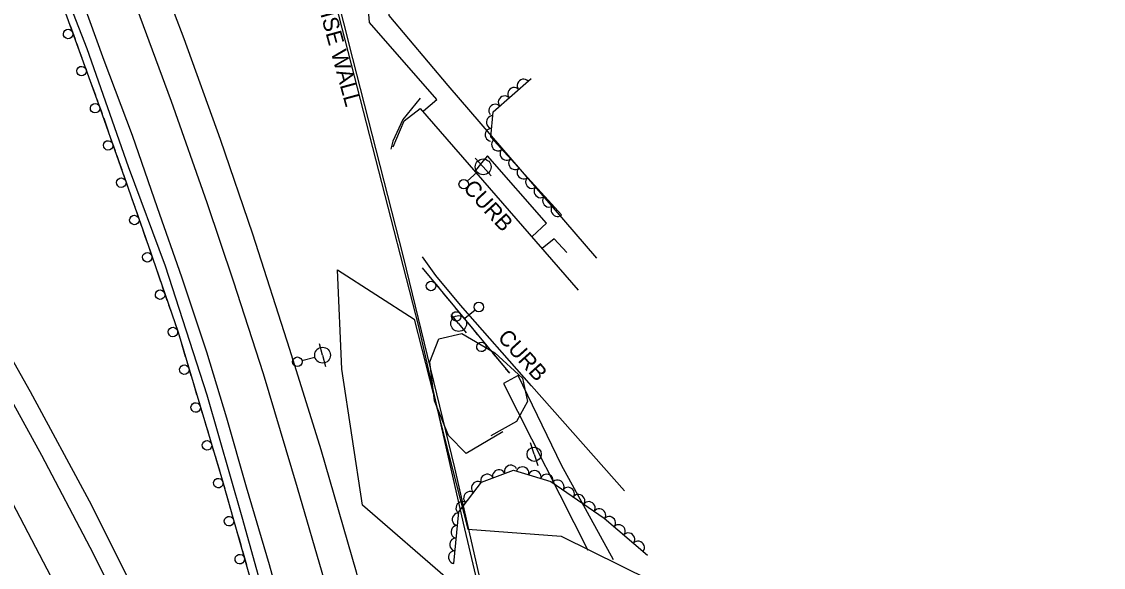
# Model space of a CAD drawing. Extents: x 1722896 to 1754269, y 648279 to 666297.
# Drawn here: x 1726282.7 to 1726624.9, y 657470 to 657642.7 of the extents above; entities that cross this region are included whole.
import ezdxf

# ---------------------------------------------------------------- set-up
doc = ezdxf.new("R2010")
doc.units = 0
for name, color, linetype in [('DESIGN - CENTERLINE - Proposed Text', 7, 'Continuous'), ('DESIGN - SCRATCH - User 1', 7, 'Continuous'), ('SURVEY - CENTERLINE - Preliminary', 7, 'Continuous'), ('SURVEY - CENTERLINE - Preliminary Text', 7, 'Continuous'), ('SURVEY - DTM - Breaklines', 7, 'Continuous'), ('SURVEY - VEGETATION - Features with Text', 7, 'Continuous')]:
    doc.layers.add(name, color=color, linetype=linetype)

msp = doc.modelspace()

# ---------------------------------------------------------------- linework, layer by layer
at = {"layer": 'DESIGN - CENTERLINE - Proposed Text'}
for points in [[(1726409.87, 657614.48), (1726414.08, 657618.02), (1726392.75, 657642.41), (1726388.25, 657697.4), (1726384.31, 657746.16), (1726380.71, 657777.8), (1726371.22, 657832.71)], [(1726378, 657832.59), (1726385.8, 657784.53), (1726390.16, 657748.13), (1726393.5, 657715.1), (1726395.2, 657683.32), (1726398.89, 657644.68), (1726417.54, 657622.52), (1726464.54, 657567.84)], [(1726444.2, 657574.69), (1726448.7, 657578.96), (1726430.09, 657600.24), (1726428.18, 657598.02), (1726425.92, 657595.15)], [(1726455.15, 657569.61), (1726451.17, 657574.02), (1726447.4, 657570.9)], [(1726439.78, 657530.69), (1726435.12, 657528.16), (1726461.82, 657475.47)], [(1726469.89, 657472.36), (1726453.51, 657502.39), (1726439.78, 657530.69)]]:
    msp.add_lwpolyline(points, dxfattribs=at)
at = {"layer": 'DESIGN - SCRATCH - User 1'}
for points in [[(1726250.96, 657761.4), (1726256.98, 657742.64), (1726264.82, 657720.98), (1726275.09, 657698.59), (1726283.23, 657679), (1726294.43, 657651.26), (1726306.95, 657616.94), (1726321.04, 657576.78), (1726332.17, 657544.39), (1726345.94, 657498.45), (1726358.6, 657453.83), (1726365.48, 657423.42), (1726367.67, 657403.38)], [(1726381, 657652.21), (1726408.22, 657546.19), (1726422.41, 657484.03), (1726439.94, 657409.35), (1726459.75, 657325.68), (1726476.24, 657252.3), (1726500.59, 657156.7), (1726516.86, 657091.32), (1726548.53, 656966.41), (1726558.67, 656932.24), (1726559.63, 656932.77), (1726548.98, 656968.62), (1726531.75, 657035.9), (1726512.24, 657113.95), (1726500.6, 657160.92), (1726473.14, 657270.05), (1726457.98, 657336.92), (1726437.8, 657422.18), (1726419.74, 657501.54), (1726403.46, 657568.29), (1726387.43, 657631.08), (1726373.33, 657687.09)], [(1726298.01, 657641.44), (1726299.59, 657637.12)], [(1726300.14, 657635.62), (1726300.94, 657633.41)], [(1726300.94, 657633.41), (1726301.75, 657631.2)], [(1726302.3, 657629.7), (1726303.87, 657625.38)], [(1726304.42, 657623.87), (1726305.23, 657621.67)], [(1726305.23, 657621.67), (1726306.03, 657619.46)], [(1726306.58, 657617.96), (1726306.95, 657616.94), (1726308.12, 657613.62)], [(1726408.74, 657618.52), (1726403.32, 657611.7), (1726400.08, 657604.84), (1726399.5, 657602.29)], [(1726308.65, 657612.11), (1726309.43, 657609.89)], [(1726309.43, 657609.89), (1726310.2, 657607.68)], [(1726310.73, 657606.17), (1726312.26, 657601.83)], [(1726312.79, 657600.32), (1726313.56, 657598.1)], [(1726313.56, 657598.1), (1726314.34, 657595.88)], [(1726314.87, 657594.37), (1726316.39, 657590.03)], [(1726316.92, 657588.52), (1726317.7, 657586.3)], [(1726317.7, 657586.3), (1726318.48, 657584.08)], [(1726319.01, 657582.58), (1726320.53, 657578.23)], [(1726321.06, 657576.72), (1726321.82, 657574.5)], [(1726321.82, 657574.5), (1726322.59, 657572.28)], [(1726323.11, 657570.77), (1726324.6, 657566.42)], [(1726325.12, 657564.9), (1726325.89, 657562.68)], [(1726325.89, 657562.68), (1726326.65, 657560.46)], [(1726409.39, 657564.81), (1726437, 657531.46)], [(1726409.39, 657564.81), (1726410.89, 657562.99)], [(1726327.17, 657558.94), (1726328.66, 657554.59)], [(1726411.91, 657561.76), (1726414.84, 657558.22)], [(1726415.86, 657556.99), (1726417.36, 657555.18)], [(1726417.36, 657555.18), (1726418.86, 657553.37)], [(1726329.18, 657553.08), (1726329.95, 657550.86)], [(1726419.88, 657552.13), (1726422.81, 657548.59)], [(1726329.95, 657550.86), (1726330.71, 657548.64)], [(1726331.23, 657547.12), (1726332.17, 657544.39), (1726332.66, 657542.75)], [(1726423.83, 657547.36), (1726425.33, 657545.55)], [(1726425.33, 657545.55), (1726426.83, 657543.74)], [(1726427.85, 657542.51), (1726430.79, 657538.96)], [(1726333.12, 657541.22), (1726333.79, 657538.97)], [(1726333.79, 657538.97), (1726334.47, 657536.72)], [(1726334.93, 657535.18), (1726336.25, 657530.78)], [(1726431.8, 657537.73), (1726433.3, 657535.92)], [(1726433.3, 657535.92), (1726434.8, 657534.11)], [(1726435.82, 657532.88), (1726437, 657531.46)], [(1726336.71, 657529.24), (1726337.38, 657526.99)], [(1726337.38, 657526.99), (1726338.06, 657524.74)], [(1726338.52, 657523.21), (1726339.84, 657518.8)], [(1726340.3, 657517.27), (1726340.97, 657515.02)], [(1726340.97, 657515.02), (1726341.65, 657512.77)], [(1726342.11, 657511.24), (1726343.43, 657506.83)], [(1726343.89, 657505.3), (1726344.56, 657503.05)], [(1726344.56, 657503.05), (1726345.24, 657500.8)], [(1726345.7, 657499.26), (1726345.94, 657498.45), (1726346.97, 657494.84)], [(1726347.4, 657493.3), (1726348.04, 657491.04)], [(1726348.04, 657491.04), (1726348.69, 657488.78)], [(1726349.12, 657487.24), (1726350.38, 657482.82)], [(1726350.81, 657481.28), (1726351.46, 657479.02)], [(1726351.46, 657479.02), (1726352.1, 657476.76)], [(1726352.53, 657475.22), (1726353.79, 657470.79)]]:
    msp.add_lwpolyline(points, dxfattribs=at)
for centre, start, end in [((1726297.38, 657638.79), 133.3123, 133.3025), ((1726301.67, 657627.04), 133.3123, 133.3025), ((1726305.93, 657615.31), 132.593, 132.5832), ((1726310.07, 657603.52), 132.593, 132.5832), ((1726314.21, 657591.72), 132.593, 132.5832), ((1726318.35, 657579.93), 132.593, 132.5832), ((1726322.43, 657568.13), 132.2196, 132.2097), ((1726412.21, 657559.05), 152.8791, 152.8692), ((1726326.49, 657556.3), 132.2196, 132.2097), ((1726420.18, 657549.42), 152.8791, 152.8692), ((1726330.55, 657544.48), 132.2196, 132.2097), ((1726428.15, 657539.79), 152.8791, 152.8692), ((1726334.15, 657532.57), 129.9498, 129.94), ((1726337.74, 657520.6), 129.9498, 129.94), ((1726341.33, 657508.62), 129.9498, 129.94), ((1726344.89, 657496.67), 129.0987, 129.0889), ((1726348.3, 657484.64), 129.0987, 129.0889), ((1726351.71, 657472.62), 129.0987, 129.0889)]:
    msp.add_arc(centre, 1.5, start, end, dxfattribs=at)
at = {"layer": 'SURVEY - CENTERLINE - Preliminary'}
msp.add_lwpolyline([(1726515.09, 657025.05), (1726489.29, 657121.29), (1726463.71, 657240.55), (1726444.45, 657331.62), (1726429.77, 657395.73), (1726418.25, 657465.7), (1726390.51, 657489.71), (1726384.01, 657532.78), (1726382.66, 657564.12), (1726406.89, 657548.59), (1726423.84, 657482.1), (1726453.33, 657479.87), (1726481.71, 657465.86), (1726509.72, 657351.89), (1726530.14, 657272.08), (1726508.58, 657266.33), (1726481.22, 657265.77), (1726497.24, 657227.31), (1726541.41, 657225.54), (1726567.72, 657118.08), (1726516.19, 657112.72), (1726535.96, 657075.42), (1726549.82, 656999.98)], dxfattribs=at)
at = {"layer": 'SURVEY - CENTERLINE - Preliminary Text'}
for points in [[(1726624.92, 656668.84), (1726597.45, 656736.24), (1726571.93, 656799.16), (1726549.81, 656855.52), (1726526.71, 656918.48), (1726505.02, 656985.71), (1726486.6, 657049.96), (1726469.03, 657114.38), (1726454.34, 657180.42), (1726441.65, 657239.2), (1726427.83, 657298.54), (1726416.2, 657352.6), (1726401.91, 657416.92), (1726388.61, 657468.49), (1726377.49, 657507.19), (1726367.56, 657538.93), (1726355.86, 657575.45), (1726345.64, 657605.36), (1726334.13, 657637.26), (1726321.92, 657669.44), (1726313.29, 657690.92), (1726305.45, 657709.59), (1726303.2, 657708.59)], [(1726411.26, 657223.24), (1726400.11, 657257.01), (1726390.99, 657282.14), (1726381.75, 657306.04), (1726373.51, 657325.94), (1726364.93, 657347.27), (1726356.75, 657365.6), (1726348.52, 657383.83), (1726339.48, 657404.47), (1726329.71, 657425.89), (1726317.16, 657450.98), (1726304.37, 657476.29), (1726289.1, 657505.38), (1726273.06, 657534.46), (1726255.11, 657565.24), (1726237.19, 657594.83), (1726218.79, 657624.35), (1726197.87, 657657.58), (1726178.77, 657685.88), (1726168.64, 657701.01)], [(1726166.72, 657676.7), (1726192.24, 657638.35), (1726215.86, 657600.47), (1726236.72, 657566.96), (1726256.68, 657532.57), (1726274.74, 657499.79), (1726291.93, 657467.18), (1726307.1, 657437.05), (1726319.24, 657412.28), (1726344.84, 657355.24), (1726355.81, 657329.47), (1726366.13, 657303.39), (1726375.2, 657279.85), (1726383.1, 657258.46), (1726390.21, 657239.04), (1726397.63, 657218.88), (1726414.95, 657166.17), (1726425.91, 657130.97), (1726435.08, 657101.5), (1726443.42, 657074.08), (1726458.04, 657025.03)], [(1726265.48, 657560.85), (1726285.34, 657525.65), (1726304.04, 657491.11), (1726323.34, 657452.56), (1726340.43, 657417.82), (1726355.1, 657385.56), (1726368.44, 657355.69), (1726380.6, 657326.49), (1726391.92, 657297.02), (1726398.76, 657281.45), (1726400.32, 657281.5), (1726400.29, 657284.6), (1726395.55, 657304.71), (1726388.44, 657337.06), (1726380.44, 657375.28), (1726372.7, 657409.5), (1726362.27, 657450.7), (1726352.51, 657485.94), (1726341.37, 657524.54), (1726328.18, 657565.3), (1726316.54, 657596.73), (1726303.39, 657634.09), (1726293.04, 657660.7)], [(1726479.82, 657034.13), (1726469.87, 657069.75), (1726461.45, 657103.35), (1726451.58, 657145.19), (1726439.56, 657196.71), (1726429.97, 657241.76), (1726418.98, 657291.07), (1726409.58, 657335.1), (1726400.61, 657376.24), (1726392.98, 657408.43), (1726385.87, 657437.45), (1726378.51, 657465.91), (1726370, 657495.16), (1726359.16, 657531.23), (1726349.73, 657560.54), (1726341.35, 657585.39), (1726330.09, 657617.43), (1726315.26, 657657.66)], [(1726301.58, 657650.09), (1726308.72, 657630.51), (1726317.62, 657606.79), (1726325.55, 657583.84), (1726333.22, 657561.92), (1726341.2, 657538.25), (1726347.52, 657517.29), (1726353.76, 657495.55), (1726360.95, 657470.97), (1726367.98, 657445.82), (1726374.84, 657418.44), (1726380.89, 657392.32), (1726385.54, 657371.4), (1726390.33, 657351.92), (1726395.56, 657326.85), (1726402.15, 657297.45), (1726409.13, 657264.23), (1726418.06, 657224.88)], [(1726400.23, 657603.03), (1726403.67, 657611.32), (1726408.77, 657615.17), (1726458.78, 657557.71)], [(1726473.39, 657494.22), (1726444, 657527.46), (1726421.54, 657553), (1726413.73, 657562.36), (1726409.49, 657568.27)]]:
    msp.add_lwpolyline(points, dxfattribs=at)
at = {"layer": 'SURVEY - DTM - Breaklines'}
for p, q in [((1726428.71, 657596.73), (1726426.21, 657599.53)), ((1726428.71, 657596.73), (1726431.2, 657593.93)), ((1726423.67, 657592.23), (1726426.84, 657595.06)), ((1726420.95, 657547.17), (1726418.57, 657550.07)), ((1726426.17, 657551.45), (1726422.88, 657548.75)), ((1726420.95, 657547.17), (1726423.32, 657544.27)), ((1726377.9, 657537.17), (1726376.96, 657540.79)), ((1726371.37, 657535.46), (1726375.48, 657536.54)), ((1726377.9, 657537.17), (1726378.85, 657533.54)), ((1726444.84, 657505.81), (1726443.72, 657509.39)), ((1726444.84, 657505.81), (1726445.95, 657502.23))]:
    msp.add_line(p, q, dxfattribs=at)
for centre, radius in [((1726428.71, 657596.73), 2.5), ((1726422.55, 657591.24), 1.5), ((1726427.33, 657552.4), 1.5), ((1726420.95, 657547.17), 2.5), ((1726377.9, 657537.17), 2.5), ((1726369.92, 657535.09), 1.5), ((1726444.84, 657505.81), 2.25)]:
    msp.add_circle(centre, radius, dxfattribs=at)
at = {"layer": 'SURVEY - VEGETATION - Features with Text'}
for points in [[(1726453.46, 657581.52), (1726431.16, 657606.09), (1726431.9, 657614.16), (1726443.88, 657624.73)], [(1726434.9, 657512.91), (1726423.28, 657506.01), (1726417.74, 657511.7), (1726413.34, 657522.74), (1726411.81, 657535.02), (1726414.66, 657542.3), (1726421.91, 657543.99), (1726432.44, 657537.86), (1726441.14, 657529.9), (1726442.71, 657522.52), (1726439.24, 657516.2), (1726431.17, 657511.65)], [(1726419.42, 657471.28), (1726421.03, 657487.58), (1726428.19, 657496.93), (1726438.31, 657500.8), (1726450.1, 657497.22), (1726466.98, 657485.63), (1726480.67, 657473.91)]]:
    msp.add_lwpolyline(points, dxfattribs=at)
for centre, major_axis in [((1726441.43, 657622.57), (1.5, 1.32)), ((1726438.43, 657619.92), (1.5, 1.32)), ((1726432.43, 657614.63), (1.5, 1.32)), ((1726435.43, 657617.28), (1.5, 1.32)), ((1726431.6, 657610.88), (0.18, 1.99)), ((1726431.23, 657606.9), (0.18, 1.99)), ((1726433.3, 657603.73), (-1.34, 1.48)), ((1726435.99, 657600.77), (-1.34, 1.48)), ((1726438.68, 657597.81), (-1.34, 1.48)), ((1726441.36, 657594.84), (-1.34, 1.48)), ((1726444.05, 657591.88), (-1.34, 1.48)), ((1726446.74, 657588.92), (-1.34, 1.48)), ((1726449.43, 657585.96), (-1.34, 1.48)), ((1726452.12, 657583), (-1.34, 1.48)), ((1726433.65, 657499.02), (1.87, 0.71)), ((1726437.39, 657500.45), (1.87, 0.71)), ((1726441.19, 657499.93), (1.91, -0.58)), ((1726445.02, 657498.77), (1.91, -0.58)), ((1726426.88, 657495.22), (1.22, 1.59)), ((1726429.91, 657497.59), (1.87, 0.71)), ((1726448.85, 657497.6), (1.91, -0.58)), ((1726452.32, 657495.7), (1.65, -1.13)), ((1726424.45, 657492.05), (1.22, 1.59)), ((1726455.62, 657493.44), (1.65, -1.13)), ((1726422.02, 657488.87), (1.22, 1.59)), ((1726458.91, 657491.17), (1.65, -1.13)), ((1726462.21, 657488.91), (1.65, -1.13)), ((1726420.8, 657485.22), (0.2, 1.99)), ((1726465.51, 657486.64), (1.65, -1.13)), ((1726420.4, 657481.23), (0.2, 1.99)), ((1726468.66, 657484.19), (1.52, -1.3)), ((1726471.7, 657481.59), (1.52, -1.3)), ((1726474.74, 657478.99), (1.52, -1.3)), ((1726420.01, 657477.25), (0.2, 1.99)), ((1726477.78, 657476.39), (1.52, -1.3)), ((1726419.62, 657473.27), (0.2, 1.99))]:
    msp.add_ellipse(centre, major_axis=major_axis, ratio=0.940188, start_param=0, end_param=3.141593, dxfattribs=at)

# ---------------------------------------------------------------- texts
at = {"layer": 'DESIGN - SCRATCH - User 1'}
for s, rotation, p in [('NOISE WALL', 285.2909, (1726374.51, 657654.86)), ('CURB', 312.4452, (1726422.12, 657589.84)), ('CURB', 312.0308, (1726433.02, 657542.56))]:
    msp.add_text(s, height=5, rotation=rotation, dxfattribs=at).set_placement(p)

doc.saveas('drawing.dxf')
